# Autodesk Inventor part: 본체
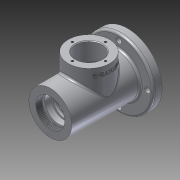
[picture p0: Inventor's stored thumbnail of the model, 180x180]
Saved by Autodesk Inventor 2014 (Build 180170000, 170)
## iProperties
Created: 2016-08
Part Number: 본체
Material: Aluminum 6061
Document SubType Name: Modeling
Designer: user
Density: 2.71 g/cm^3
Appearance: Aluminum - Flat
Mass: 765.865 g
Surface Area: 621.286 cm^2
Volume: 282.607 cm^3
Author: user
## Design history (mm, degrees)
sketch "Sketch1"
  geometry: C1 r 31 at (0, 0); 1 further point
  constraints: 1 centre point, 1 coincident
  dimensions: "d0" = 62 diameter of C1
extrude "Extrusion1" new body sketch "Sketch1" distance "d1" = 115; taper "d2" = 0 deg
workplane "Work Plane1"
sketch "Sketch2"
  geometry: C1 r 50 at (0, 0); 1 further point
  constraints: 1 centre point, 1 coincident
  dimensions: "d4" = 100 diameter of C1
extrude "Extrusion2" join sketch "Sketch2" distance "d5" = 13; taper "d6" = 0 deg
sketch "Sketch3"
  geometry: L1 (0, 41.5)-(41.5, 0); L2 (41.5, 0)-(0, -41.5); L3 (0, -41.5)-(-41.5, 0); L4 (-41.5, 0)-(0, 41.5); C1 r 31 at (0, 0) reference; 5 further points
  constraints: 8 end point, 5 coincident, 1 vertical alignment, 9 other
  dimensions: "d7" = 83 distance of L1.start L2.end
hole "Hole1" sketch "Sketch3" at (0, 41.5), (-41.5, 0), (0, -41.5), (41.5, 0) diameter "d8" = 8; stored, may be unused: countersink angle "d12" = 90 deg, drill point angle "d14" = 118 deg; dims "d9" = 6, "d10" = 4, "d11" = 2, "d13" = 8
sketch "Sketch4"
  geometry: C1 r 31 at (0, 0) reference; C2 r 21 at (0, 0)
  constraints: 1 centre point, 1 coincident
extrude "Extrusion3" cut sketch "Sketch4" distance "d15" = 9; taper "d16" = 0 deg
sketch "Sketch5"
  geometry: C1 r 21 at (0, 0) reference; C2 r 24 at (0, 0)
  constraints: 1 centre point, 1 coincident
extrude "Extrusion4" cut sketch "Sketch5" distance "d17" = 3; taper "d18" = 0 deg
sketch "Sketch6"
  geometry: C1 r 24 at (0, 0) reference; C2 r 20 at (0, 0)
  constraints: 1 centre point, 1 coincident
extrude "Extrusion5" cut sketch "Sketch6" distance "d19" = 9; taper "d20" = 0 deg
sketch "Sketch7"
  geometry: C1 r 20 at (0, 0) reference; C2 r 17.5 at (0, 0)
  constraints: 1 centre point, 1 coincident
extrude "Extrusion6" cut sketch "Sketch7" distance "d21" = 3.25; taper "d22" = 0 deg
sketch "Sketch8"
  geometry: C1 r 17.5 at (0, 0) reference; C2 r 18.5 at (0, 0)
  constraints: 1 centre point, 1 coincident
  dimensions: "d23" = 37 diameter of C2
extrude "Extrusion7" cut sketch "Sketch8" distance "d24" = 1.75; taper "d25" = 0 deg
sketch "Sketch9"
  geometry: L1 (26, -18.5)-(26, 18.5) reference; L2 (26, -17.5)-(36, -17.5); L3 (37, -18.5)-(37, -23); L4 (40, -26)-(72, -26); L5 (75, -23)-(75, -18.5); L6 (76, -17.5)-(85.7, -17.5); L7 (86, -17.2)-(86, -16.5); L8 (86, -16.5)-(88, -16.5); L9 (91, -13.5)-(91, -10); L10 (91, -10)-(93.7, -10); L11 (93.7, -10)-(93.7, -12.2); L12 (94, -12.5)-(100.3, -12.5); L13 (101, -12.904)-(101, -13.886); L14 (102.991, -16.711)-(115, -21); L15 (115, -31)-(115, 31) reference; L16 (26, 0)-(115, 0); L17 (100.3, -12.5)-(101, -12.904); L18 (36, -17.5)-(37, -18.5); L19 (75, -18.5)-(76, -17.5); L20 (26, -17.5)-(26, 0); L21 (115, -21)-(115, 0); A1 r 0.3 centre (85.7, -17.2) between (85.7, -17.5) and (86, -17.2); A2 r 0.3 centre (94, -12.2) between (93.7, -12.2) and (94, -12.5); A3 r 3 centre (88, -13.5) between (88, -16.5) and (91, -13.5); A4 r 3 centre (104, -13.886) between (101, -13.886) and (102.991, -16.711); A5 r 3 centre (40, -23) between (37, -23) and (40, -26); A6 r 3 centre (72, -23) between (72, -26) and (75, -23); 5 further points
  constraints: 38 end point, 12 point on circle, 12 tangent, 10 point on line, 6 centre point, 2 midpoint, 1 equal radius
  dimensions: "d26" = 35 diameter of L2 L16; "d27" = 52 diameter of L4 L16; "d28" = 35 diameter of L6 L16; "d29" = 33 diameter of L8 L16; "d30" = 0.3 radius of A1; "d31" = 20 diameter of L10 L16; "d32" = 25 diameter of L12 L16; "d33" = 0.3 radius of A2; "d34" = 38 distance between parallel lines of L5 L3; "d35" = 60 distance between parallel lines of L7 L1; "d36" = 3 radius of A3; "d37" = 2.7 distance of L9.end L10.end; "d38" = 42 diameter of L14.end L16; "d39" = 32 diameter of point (101, -16) L16; "d40" = 14 distance between parallel lines of L15 L13; "d42" = 7.3 distance between parallel lines of L13 L11; "d43" = 0.7 distance of L12.end point (101, -12.5); "d44" = 30 deg angle of L12 L17; "d45" = 3 radius of A4; "d46" = 5 distance between parallel lines of L9 L7 (derived); "d47" = 3 radius of A5; "d48" = 1 distance of L2.end point (37, -17.5); "d49" = 1 distance of L3.start point (37, -17.5) (= d48); "d50" = 1 distance of L5.end point (75, -17.5) (= d48); "d51" = 1 distance of L6.start point (75, -17.5) (= d50); "d52" = 11 distance between parallel lines of L1 L3 (= -0.5 x d34 + 0.5 x d35)
revolve "Revolution1" sketch "Sketch9" stored, may be unused: angle "d53" = 90 deg
workplane "Work Plane2"
sketch "Sketch10"
  geometry: C1 r 30 at (0, 56); 1 further point
  constraints: 1 centre point, 1 vertical alignment
  dimensions: "d55" = 60 diameter of C1; "d56" = 56 distance of C1.centre point (0, 0)
extrude "Extrusion8" join sketch "Sketch10" stored distance "d57" = 1.75; taper "d58" = 0 deg
fillet "Fillet1" dims "d59" = 3
sketch "Sketch11"
  geometry: C1 r 30 at (0, 0) reference; C2 r 19 at (0, 0); 1 further point
  constraints: 1 centre point, 1 coincident
  dimensions: "d60" = 38 diameter of C2
extrude "Extrusion9" cut sketch "Sketch11" stored distance "d61" = 1.75; taper "d62" = 0 deg
chamfer "Chamfer1" distance "d63" = 1; stored, may be unused: second distance "d64" = 2, angle "d65" = 45 deg
sketch "Sketch12"
  geometry: L1 (-24, 0)-(0, 24); L2 (0, 24)-(24, 0); L3 (24, 0)-(0, -24); L4 (0, -24)-(-24, 0); C1 r 20 at (0, 0) reference; 6 further points
  constraints: 8 end point, 5 coincident, 1 horizontal alignment, 9 other
  dimensions: "d66" = 48 distance of L2.end L1.start
hole "Hole2" sketch "Sketch12" at (0, 24), (-24, 0), (0, -24), (24, 0) diameter "d67" = 3.242; stored, may be unused: countersink angle "d71" = 90 deg, drill point angle "d73" = 118 deg; dims "d68" = 8, "d69" = 4, "d70" = 2, "d72" = 10
fillet "Fillet2" dims "d74" = 3
thread "Thread1" dims "d75" = 10, "d76" = 0
workplane "Work Plane3"
sketch "Sketch13"
  geometry: L1 (-30, 0)-(30, 0) reference; 2 further points
  constraints: 1 other
  dimensions: "d77" = 56 horizontal distance of point (0, -10) point (-56, -49); "d78" = 10 distance from line of L1 point (0, -10)
emboss "Emboss1" sketch "Sketch13" dims "d1" = 115, "d2" = 0, "d79" = 0.5, "d80" = 0
fillet "Fillet3" dims "d81" = 3
body "Solid1"
other parameters: "d3" = -3, "d54" = 49
